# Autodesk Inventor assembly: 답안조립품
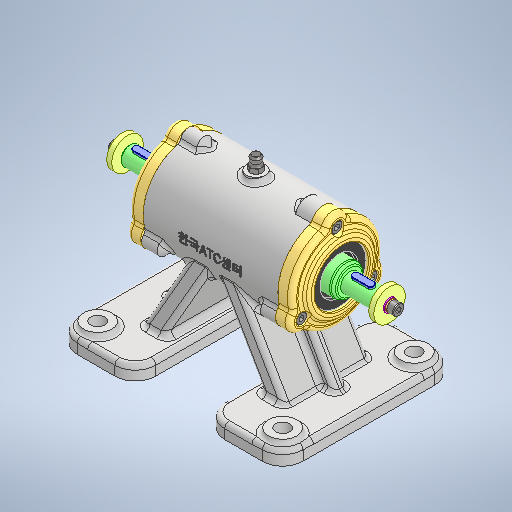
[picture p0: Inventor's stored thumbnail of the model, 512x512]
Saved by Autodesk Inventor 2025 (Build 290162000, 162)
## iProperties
Created: 2026-04
Part Number: 답안조립품
Document SubType Name: Assembly
Designer: KDI
Author: KDI
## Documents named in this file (17)
- C:\Users\KDI\Desktop\760403V1011\답안조립품.iam
- C:\Users\KDI\Desktop\760403V1011\본체.ipt
- C:\Users\KDI\Desktop\760403V1011\6각 구멍붙이 볼트 M4x12\6각 구멍붙이 볼트 M4x12.ipt
- C:\Users\KDI\Desktop\760403V1011\그리스 니플 M6x0,75\그리스 니플 M6x0,75.ipt
- C:\Users\KDI\Desktop\760403V1011\깊은 홈 볼 베어링 6004\깊은 홈 볼 베어링 6004.ipt
- C:\Users\KDI\Desktop\760403V1011\스퍼 기어\스퍼 기어.ipt
- C:\Users\KDI\Desktop\760403V1011\스프링 와셔 M4\스프링 와셔 M4.ipt
- C:\Users\KDI\Desktop\760403V1011\실링\실링.ipt
- C:\Users\KDI\Desktop\760403V1011\엔드 캡\엔드 캡.ipt
- C:\Users\KDI\Desktop\760403V1011\오일 실 20 35 8\오일 실 20 35 8.ipt
- C:\Users\KDI\Desktop\760403V1011\축\축.ipt
- C:\Users\KDI\Desktop\760403V1011\커버\커버.ipt
- C:\Users\KDI\Desktop\760403V1011\평 와셔 M4\평 와셔 M4.ipt
- C:\Users\KDI\Desktop\760403V1011\평행 키 4x4x14\평행 키 4x4x14.ipt
- C:\Users\KDI\Desktop\760403V1011\플랜지\플랜지.ipt
- C:\Users\KDI\Desktop\760403V1011\플러그 M6x0,75\플러그 M6x0,75.ipt
- C:\Users\KDI\Desktop\760403V1011\6각 구멍붙이 볼트 M4x12\6각 구멍붙이 볼트 M4x12_MIR.ipt
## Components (11 placed, 5 different names)
1. 6각 구멍붙이 볼트 M4x12:1
2. 그리스 니플 M6x0,75:1
3. 플랜지:1
4. 플러그 M6x0,75:1
5. 6각 구멍붙이 볼트 M4x12:2
6. 6각 구멍붙이 볼트 M4x12_MIR:1
7. 6각 구멍붙이 볼트 M4x12_MIR:2
8. 6각 구멍붙이 볼트 M4x12_MIR:3
9. 6각 구멍붙이 볼트 M4x12:3
10. 6각 구멍붙이 볼트 M4x12:4
11. 6각 구멍붙이 볼트 M4x12:5
